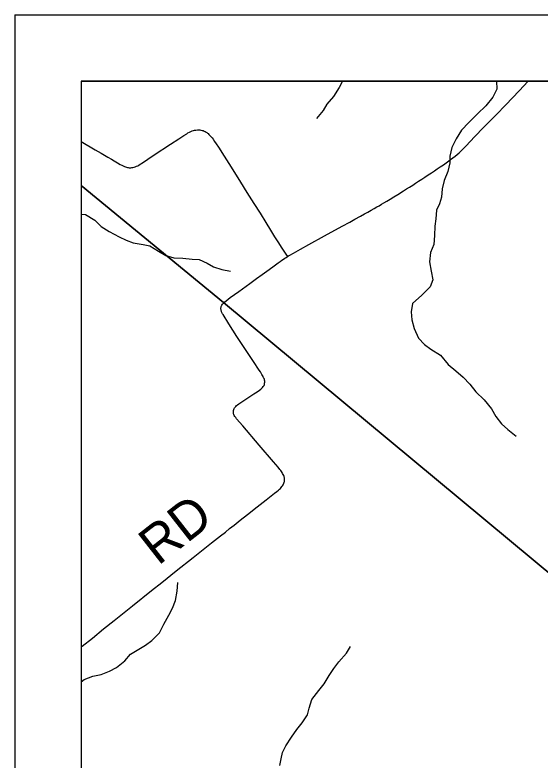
# Model space of a CAD drawing. Extents: x 0 to 34, y 0 to 22.
# Drawn here: x 2 to 2.791, y 19.877 to 21 of the extents above; entities that cross this region are included whole.
import ezdxf

# ---------------------------------------------------------------- set-up
doc = ezdxf.new("R2010")
doc.units = 0
for name, color, linetype in [('GM_X_Minor_River', 7, 'Continuous'), ('GM_X_Township_Road', 7, 'Continuous'), ('GM_X_Township_Road_Text', 7, 'Continuous'), ('SH_Data', 7, 'Continuous')]:
    doc.layers.add(name, color=color, linetype=linetype)

msp = doc.modelspace()

# ---------------------------------------------------------------- linework, layer by layer
at = {"layer": 'GM_X_Minor_River'}
for points in [[(2.4936, 20.9), (2.4885, 20.8904), (2.4803, 20.8769), (2.4702, 20.8657), (2.4647, 20.8559), (2.4546, 20.844)], [(2.7259, 20.9), (2.726, 20.8879), (2.7201, 20.8759), (2.7096, 20.8628), (2.6972, 20.851), (2.6841, 20.8379), (2.6732, 20.8264), (2.665, 20.8133), (2.6583, 20.8001), (2.6554, 20.7873), (2.6552, 20.777), (2.6522, 20.7642), (2.647, 20.7506), (2.6441, 20.7378), (2.6427, 20.7253), (2.6399, 20.7155), (2.6355, 20.7057), (2.6341, 20.6928), (2.6327, 20.6815), (2.6325, 20.6678), (2.6314, 20.6538), (2.6262, 20.6418), (2.6248, 20.6278), (2.6272, 20.6137), (2.6296, 20.6007), (2.6256, 20.5902), (2.6132, 20.5779), (2.5993, 20.5653), (2.5971, 20.5524), (2.5984, 20.5407), (2.6015, 20.5273), (2.6081, 20.5128), (2.617, 20.5031), (2.6267, 20.4965), (2.6413, 20.4871), (2.6531, 20.4732), (2.6646, 20.4635), (2.6754, 20.4541), (2.6858, 20.4437), (2.6947, 20.4318), (2.7073, 20.4197), (2.7184, 20.4066), (2.7246, 20.3947), (2.7331, 20.3836), (2.7428, 20.3754), (2.7555, 20.3653)], [(2.1, 20.6998), (2.1065, 20.6991), (2.1203, 20.6909), (2.13, 20.6812), (2.1423, 20.6734), (2.157, 20.6655), (2.1678, 20.6603), (2.1784, 20.6567), (2.1931, 20.6538), (2.2033, 20.652), (2.2164, 20.6438), (2.2272, 20.6372), (2.2397, 20.6339), (2.2533, 20.6332), (2.2669, 20.6318), (2.2779, 20.6312), (2.2895, 20.6257), (2.2992, 20.6202), (2.3117, 20.6161), (2.3249, 20.614)], [(2.1, 19.9952), (2.1046, 19.9984), (2.1176, 20.0034), (2.1302, 20.0062), (2.1428, 20.0109), (2.1531, 20.0164), (2.1655, 20.0268), (2.1744, 20.0368), (2.1966, 20.0501), (2.2062, 20.0571), (2.2178, 20.069), (2.2242, 20.0818), (2.232, 20.0956), (2.2375, 20.1058), (2.242, 20.1175), (2.2445, 20.1318), (2.2455, 20.1447)], [(2.3994, 19.8689), (2.4011, 19.8787), (2.4032, 19.8885), (2.4083, 19.8987), (2.4169, 19.9118), (2.4247, 19.923), (2.4329, 19.9331), (2.4411, 19.9451), (2.4432, 19.9553), (2.4476, 19.9681), (2.4581, 19.9819), (2.4659, 19.992), (2.4738, 20.0047), (2.4804, 20.0152), (2.4882, 20.0253), (2.4998, 20.0384), (2.5057, 20.0481)]]:
    msp.add_lwpolyline(points, dxfattribs=at)
at = {"layer": 'GM_X_Township_Road'}
msp.add_lwpolyline([(4.4664, 20.9), (2.1, 20.9), (2.1, 20.7431), (2.3144, 20.5665), (3.1019, 19.912), (3.1735, 19.8394), (3.4805, 19.8366), (3.501, 19.6889), (4.4654, 19.6041), (4.4849, 19.6021), (4.4684, 20.7448)], close=True, dxfattribs=at)
for points in [[(2.4106, 20.6359), (2.4123, 20.6368), (2.4144, 20.6381), (2.4198, 20.6411), (2.4304, 20.647), (2.4427, 20.6538), (2.4665, 20.667), (2.4933, 20.6816), (2.5048, 20.6879), (2.5123, 20.692), (2.5207, 20.6967), (2.527, 20.7002), (2.5319, 20.7029), (2.5368, 20.7057), (2.5414, 20.7083), (2.5455, 20.7106), (2.5488, 20.7125), (2.5524, 20.7146), (2.556, 20.7168), (2.5605, 20.7194), (2.5655, 20.7225), (2.571, 20.7258), (2.577, 20.7295), (2.5854, 20.7348), (2.59, 20.7377), (2.5946, 20.7405), (2.5995, 20.7436), (2.6037, 20.7463), (2.6082, 20.7492), (2.613, 20.7524), (2.6175, 20.7553), (2.623, 20.759), (2.6278, 20.7621), (2.6321, 20.765), (2.6364, 20.7679), (2.6408, 20.7709), (2.6458, 20.7743), (2.6499, 20.7772), (2.6537, 20.7799), (2.6566, 20.7821), (2.6598, 20.7844), (2.6634, 20.7872), (2.6664, 20.7897), (2.6694, 20.7923), (2.6725, 20.7953), (2.6749, 20.7977), (2.677, 20.7999), (2.6794, 20.8024), (2.6932, 20.8169), (2.7063, 20.8304), (2.7254, 20.8495), (2.7399, 20.8643), (2.75, 20.8749), (2.7601, 20.8858), (2.7733, 20.9)], [(2.1, 20.8091), (2.121, 20.7968), (2.13, 20.7915), (2.1402, 20.7855), (2.1454, 20.7825), (2.1497, 20.78), (2.1548, 20.7771), (2.1588, 20.7748), (2.1609, 20.7736), (2.163, 20.7726), (2.165, 20.7716), (2.1668, 20.7708), (2.1682, 20.7704), (2.1696, 20.7701), (2.1709, 20.7698), (2.1722, 20.7697), (2.1733, 20.7696), (2.1746, 20.7696), (2.1761, 20.7698), (2.1779, 20.7701), (2.1798, 20.7706), (2.1813, 20.7711), (2.1831, 20.7718), (2.1853, 20.7728), (2.1869, 20.7737), (2.1889, 20.7749), (2.1906, 20.7759), (2.21, 20.7891), (2.2346, 20.8054), (2.2468, 20.8134), (2.2547, 20.8184), (2.2589, 20.821), (2.2608, 20.8221), (2.2632, 20.8234), (2.2652, 20.8244), (2.2671, 20.8253), (2.2691, 20.8259), (2.2707, 20.8262), (2.2725, 20.8265), (2.275, 20.8266), (2.2768, 20.8266), (2.2787, 20.8266), (2.2804, 20.8264), (2.2823, 20.826), (2.2837, 20.8256), (2.2853, 20.8249), (2.2866, 20.8243), (2.288, 20.8234), (2.2893, 20.8226), (2.2902, 20.822), (2.2913, 20.8211), (2.2924, 20.82), (2.2934, 20.8189), (2.2944, 20.8179), (2.2951, 20.817), (2.2959, 20.8161), (2.2972, 20.8146), (2.2987, 20.8126), (2.301, 20.8093), (2.3035, 20.8056), (2.3067, 20.8008), (2.3153, 20.7871), (2.3224, 20.7761), (2.331, 20.7625), (2.3401, 20.7479), (2.3495, 20.7325), (2.3602, 20.7157), (2.3694, 20.7011), (2.3782, 20.6871), (2.3853, 20.6756), (2.3913, 20.6657), (2.3971, 20.6567), (2.4014, 20.6501), (2.4083, 20.6393), (2.4106, 20.6359)], [(3.7787, 17.0143), (3.7921, 17.074), (3.9903, 17.6899), (4.0744, 17.9948), (4.1901, 18.4135), (4.1943, 18.4289), (4.2897, 18.7747), (4.3389, 18.9527), (4.4789, 19.5742), (4.4849, 19.6021), (4.4654, 19.6041), (3.501, 19.6889), (3.4805, 19.8366), (3.1735, 19.8394), (3.1019, 19.912), (2.3144, 20.5665), (2.1, 20.7431), (2.1, 15.597), (2.2517, 15.5643), (3.1228, 15.3686), (3.3385, 15.3189), (3.6691, 16.5264), (3.7277, 16.7873)], [(2.3146, 20.5659), (2.3164, 20.5676), (2.3185, 20.5693), (2.3246, 20.5739), (2.3377, 20.5834), (2.3538, 20.5951), (2.3643, 20.6026), (2.3726, 20.6087), (2.3833, 20.6164), (2.3905, 20.6217), (2.3967, 20.6262), (2.3999, 20.6285), (2.4025, 20.6303), (2.405, 20.6321), (2.4069, 20.6334), (2.4087, 20.6346), (2.4106, 20.6359)], [(2.3477, 20.4958), (2.3346, 20.5156), (2.3226, 20.5343), (2.3136, 20.5483), (2.3128, 20.5496), (2.3122, 20.5506), (2.3117, 20.5516), (2.3114, 20.5526), (2.3111, 20.5535), (2.3108, 20.5545), (2.3107, 20.5554), (2.3105, 20.5566), (2.3104, 20.5578), (2.3105, 20.5588), (2.3106, 20.5597), (2.3108, 20.5608), (2.3113, 20.5618), (2.3119, 20.5628), (2.3127, 20.564), (2.3136, 20.565), (2.3146, 20.5659)], [(2.1, 20.0477), (2.1013, 20.0487), (2.1168, 20.061), (2.1337, 20.0747), (2.1496, 20.0874), (2.1771, 20.1094), (2.2059, 20.1324), (2.2212, 20.1448), (2.2429, 20.1623), (2.2688, 20.1824), (2.2965, 20.2043), (2.3099, 20.2148), (2.3172, 20.2207), (2.3236, 20.2259), (2.3302, 20.2311), (2.3397, 20.2387), (2.3503, 20.2471), (2.3651, 20.2585), (2.3788, 20.2692), (2.3914, 20.2792), (2.3949, 20.2819), (2.3972, 20.2838), (2.3988, 20.2852), (2.4, 20.2865), (2.4012, 20.2877), (2.4024, 20.2892), (2.4033, 20.2904), (2.4041, 20.2917), (2.4048, 20.2929), (2.4053, 20.2941), (2.4058, 20.2957), (2.4061, 20.2971), (2.4063, 20.2985), (2.4064, 20.2999), (2.4063, 20.3011), (2.4061, 20.3025), (2.406, 20.3035), (2.4056, 20.3045), (2.4051, 20.3059), (2.4043, 20.3075), (2.4035, 20.309), (2.4027, 20.3103), (2.4017, 20.3118), (2.4006, 20.3133), (2.3994, 20.3148), (2.3967, 20.3182), (2.3899, 20.3263), (2.3681, 20.3517), (2.3436, 20.3805), (2.334, 20.3915), (2.3327, 20.3932), (2.3315, 20.3949), (2.3305, 20.3965), (2.33, 20.3977), (2.3296, 20.3989), (2.3293, 20.4005), (2.3292, 20.4015), (2.3292, 20.4028), (2.3293, 20.4039), (2.3297, 20.4052), (2.3303, 20.4067), (2.331, 20.4078), (2.3318, 20.4089), (2.3328, 20.4099), (2.334, 20.4112), (2.3356, 20.4125), (2.3373, 20.4138), (2.3437, 20.4181), (2.3603, 20.4288), (2.3653, 20.4321), (2.3684, 20.4343), (2.3704, 20.4359), (2.3719, 20.4373), (2.3731, 20.4385), (2.3742, 20.4398), (2.3749, 20.4408), (2.3754, 20.4417), (2.3759, 20.4432), (2.3762, 20.4449), (2.3764, 20.4464), (2.3764, 20.448), (2.3762, 20.4495), (2.3759, 20.4508), (2.3754, 20.452), (2.3748, 20.4533), (2.3741, 20.4549), (2.3733, 20.4564), (2.3722, 20.4583), (2.371, 20.4602), (2.3699, 20.4621), (2.3683, 20.4645), (2.3598, 20.4777), (2.3477, 20.4958)]]:
    msp.add_lwpolyline(points, dxfattribs=at)
at = {"layer": 'SH_Data'}
for p, q in [((2, 21), (9, 21)), ((2, 21), (2, 14)), ((2.1, 20.9), (2.1, 14.1)), ((2.1, 20.9), (8.9, 20.9))]:
    msp.add_line(p, q, dxfattribs=at)

# ---------------------------------------------------------------- texts
at = {"layer": 'GM_X_Township_Road_Text'}
msp.add_text('RD', height=0.05682, rotation=38.0427, dxfattribs=at).set_placement((2.2157, 20.1691))

doc.saveas('drawing.dxf')
